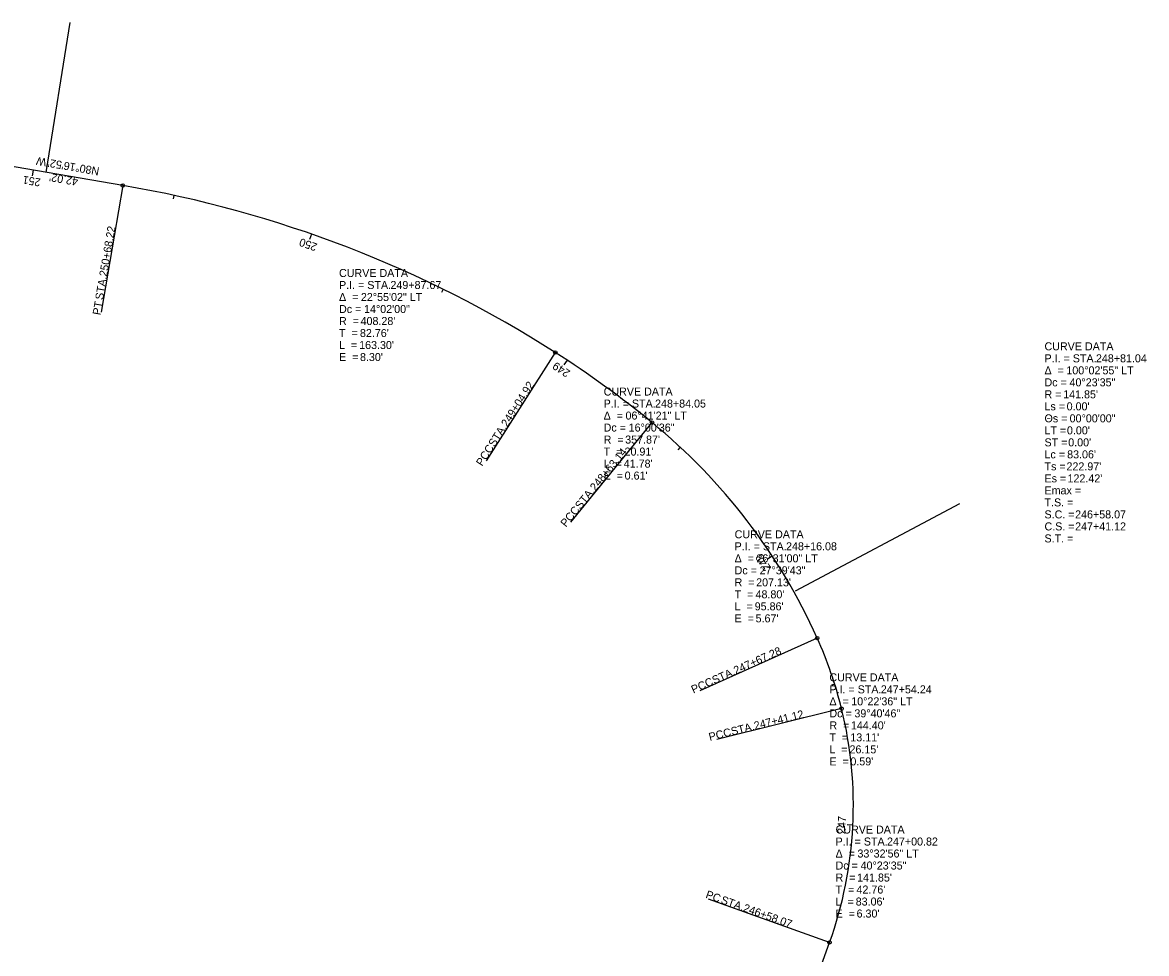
# Model space of a CAD drawing. Extents: x 2479470 to 2480226, y 287083 to 287867.
# Drawn here: x 2479832.4 to 2480225.6, y 287464.3 to 287790 of the extents above; entities that cross this region are included whole.
import ezdxf

# ---------------------------------------------------------------- set-up
doc = ezdxf.new("R2010")
doc.units = 0
for name, color, linetype in [('Default', 7, 'Continuous'), ('DV_X_Lot_Line', 7, 'Continuous'), ('DV_X_Property_Line', 7, 'Continuous'), ('GE_X_Alignment_100_Cardinal_Points', 7, 'Continuous'), ('GE_X_Alignment_100_Curve_Data', 7, 'Continuous'), ('GE_X_Alignment_100_Distances', 7, 'Continuous'), ('GE_X_Alignment_100_Stations', 7, 'Continuous')]:
    doc.layers.add(name, color=color, linetype=linetype)

msp = doc.modelspace()

# ---------------------------------------------------------------- linework, layer by layer
at = {"layer": 'Default'}
msp.add_line((2480102.75, 287591.14), (2480160.32, 287621.66), dxfattribs=at)
msp.add_lwpolyline([(2479840.68, 287737.46), (2479840.79, 287738.22), (2479849.04, 287789.97)], dxfattribs=at)
at = {"layer": 'DV_X_Lot_Line'}
for p, q in [((2479867.44, 287732.95), (2479826.02, 287740.04)), ((2480091.52, 287403.39), (2480114.72, 287468.16))]:
    msp.add_line(p, q, dxfattribs=at)
for centre, radius, start, end in [((2479798.95, 287330.45), 408.28, 57.4266, 80.3437), ((2479826.09, 287372.93), 357.87, 50.7375, 57.4266), ((2479921.5, 287489.65), 207.13, 24.2208, 50.7375), ((2479978.7, 287515.38), 144.4, 13.844, 24.2208), ((2479981.18, 287515.99), 141.85, 340.2952, 13.844)]:
    msp.add_arc(centre, radius, start, end, dxfattribs=at)
at = {"layer": 'GE_X_Alignment_100_Cardinal_Points'}
for p, q in [((2479867.44, 287732.95), (2479859.84, 287688.59)), ((2480018.76, 287674.51), (2479994.54, 287636.59)), ((2480052.58, 287650.02), (2480024.1, 287615.17)), ((2480110.39, 287574.62), (2480069.35, 287556.16)), ((2480118.91, 287549.93), (2480075.21, 287539.16)), ((2480114.72, 287468.16), (2480072.36, 287483.34))]:
    msp.add_line(p, q, dxfattribs=at)
for centre in [(2479867.44, 287732.95), (2480018.76, 287674.51), (2480052.58, 287650.02), (2480110.39, 287574.62), (2480118.91, 287549.93), (2480114.72, 287468.16)]:
    msp.add_circle(centre, 0.6, dxfattribs=at)
at = {"layer": 'GE_X_Alignment_100_Stations'}
for p, q in [((2479836.11, 287738.31), (2479835.78, 287736.34)), ((2479885.33, 287729.49), (2479885.07, 287728.32)), ((2479933.42, 287715.95), (2479932.77, 287714.06)), ((2479979.51, 287696.64), (2479978.98, 287695.56)), ((2480022.89, 287671.84), (2480021.79, 287670.17)), ((2480062.48, 287641.39), (2480061.66, 287640.51)), ((2480094.67, 287603.28), (2480093, 287602.18)), ((2480116.52, 287558.48), (2480115.37, 287558.12)), ((2480122.86, 287509.14), (2480120.86, 287509.24))]:
    msp.add_line(p, q, dxfattribs=at)

# ---------------------------------------------------------------- texts
at = {"layer": 'DV_X_Property_Line'}
msp.add_text('N80°16\'52"W', height=2.8, rotation=170.2811, dxfattribs=at).set_placement((2479859.4, 287739.19))
at = {"layer": 'GE_X_Alignment_100_Cardinal_Points'}
for s, rotation, p in [('250+68.22', 80.2811, (2479861.92, 287700.94)), (' STA. ', 80.2811, (2479860.34, 287691.75)), ('PT', 80.2811, (2479859.61, 287687.46)), ('249+04.92', 57.4266, (2480001.95, 287648.26)), (' STA. ', 57.4266, (2479996.93, 287640.4)), ('PCC', 57.4266, (2479993.18, 287634.53)), ('248+63.14', 50.7375, (2480032.78, 287625.85)), (' STA. ', 50.7375, (2480026.88, 287618.63)), ('PCC', 50.7375, (2480022.47, 287613.24)), ('247+67.28', 24.2208, (2480081.91, 287561.85)), (' STA. ', 24.2208, (2480073.41, 287558.02)), ('PCC', 24.2208, (2480067.06, 287555.17)), ('247+41.12', 13.844, (2480088.63, 287542.51)), (' STA. ', 13.844, (2480079.57, 287540.28)), ('PCC', 13.844, (2480072.82, 287538.61)), ('PC', 340.2952, (2480071.13, 287483.81)), (' STA. ', 340.2952, (2480075.46, 287482.26)), ('246+58.07', 340.2952, (2480084.24, 287479.12))]:
    msp.add_text(s, height=2.8, rotation=rotation, dxfattribs=at).set_placement(p)
at = {"layer": 'GE_X_Alignment_100_Curve_Data'}
for s, p in [('CURVE DATA', (2479943.1, 287700.93)), ('P.I. = STA. ', (2479943.1, 287696.73)), ('249+87.67', (2479961.09, 287696.73)), ('Δ  = ', (2479943.1, 287692.53)), ('22°55\'02" LT', (2479950.75, 287692.53)), ('Dc = ', (2479943.1, 287688.33)), ('14°02\'00"', (2479951.85, 287688.33)), ('R  = ', (2479943.1, 287684.13)), ("408.28'", (2479950.64, 287684.13)), ('T  = ', (2479943.1, 287679.93)), ("82.76'", (2479950.42, 287679.93)), ('L  = ', (2479943.1, 287675.73)), ("163.30'", (2479950.14, 287675.73)), ('CURVE DATA', (2480189.9, 287675.28)), ('E  = ', (2479943.1, 287671.53)), ("8.30'", (2479950.44, 287671.53)), ('P.I. = STA. ', (2480189.9, 287671.08)), ('248+81.04', (2480207.89, 287671.08)), ('Δ  = ', (2480189.9, 287666.88)), ('100°02\'55" LT', (2480197.55, 287666.88)), ('CURVE DATA', (2480035.67, 287659.46)), ('Dc = ', (2480189.9, 287662.68)), ('40°23\'35"', (2480198.65, 287662.68)), ('P.I. = STA. ', (2480035.67, 287655.26)), ('248+84.05', (2480053.66, 287655.26)), ('R = ', (2480189.9, 287658.48)), ("141.85'", (2480196.44, 287658.48)), ('Δ  = ', (2480035.67, 287651.06)), ('06°41\'21" LT', (2480043.32, 287651.06)), ('Ls = ', (2480189.9, 287654.28)), ("0.00'", (2480197.65, 287654.28)), ('Θs = ', (2480189.9, 287650.08)), ('00°00\'00"', (2480198.69, 287650.08)), ('Dc = ', (2480035.67, 287646.86)), ('16°00\'36"', (2480044.42, 287646.86)), ('LT = ', (2480189.9, 287645.88)), ("0.00'", (2480197.75, 287645.88)), ('R  = ', (2480035.67, 287642.66)), ("357.87'", (2480043.21, 287642.66)), ('ST = ', (2480189.9, 287641.68)), ("0.00'", (2480198.2, 287641.68)), ('T  = ', (2480035.67, 287638.46)), ("20.91'", (2480042.99, 287638.46)), ('Lc = ', (2480189.9, 287637.48)), ("83.06'", (2480197.82, 287637.48)), ('L  = ', (2480035.67, 287634.26)), ("41.78'", (2480042.71, 287634.26)), ('Ts = ', (2480189.9, 287633.28)), ("222.97'", (2480197.59, 287633.28)), ('E  = ', (2480035.67, 287630.06)), ("0.61'", (2480043.02, 287630.06)), ('Es = ', (2480189.9, 287629.08)), ("122.42'", (2480197.95, 287629.08)), ('Emax = ', (2480189.9, 287624.88)), ('T.S. = ', (2480189.9, 287620.68)), ('S.C. = ', (2480189.9, 287616.48)), ('246+58.07', (2480200.61, 287616.48)), ('C.S. = ', (2480189.9, 287612.28)), ('247+41.12', (2480200.61, 287612.28)), ('CURVE DATA', (2480081.49, 287609.52)), ('S.T. = ', (2480189.9, 287608.08)), ('P.I. = STA. ', (2480081.49, 287605.32)), ('248+16.08', (2480099.48, 287605.32)), ('Δ  = ', (2480081.49, 287601.12)), ('26°31\'00" LT', (2480089.13, 287601.12)), ('Dc = ', (2480081.49, 287596.92)), ('27°39\'43"', (2480090.23, 287596.92)), ('R  = ', (2480081.49, 287592.72)), ("207.13'", (2480089.02, 287592.72)), ('T  = ', (2480081.49, 287588.52)), ("48.80'", (2480088.81, 287588.52)), ('L  = ', (2480081.49, 287584.32)), ("95.86'", (2480088.52, 287584.32)), ("5.67'", (2480088.83, 287580.12)), ('E  = ', (2480081.49, 287580.12)), ('CURVE DATA', (2480114.65, 287559.48)), ('P.I. = STA. ', (2480114.65, 287555.28)), ('247+54.24', (2480132.64, 287555.28)), ('Δ  = ', (2480114.65, 287551.08)), ('10°22\'36" LT', (2480122.29, 287551.08)), ('Dc = ', (2480114.65, 287546.88)), ('39°40\'46"', (2480123.39, 287546.88)), ('R  = ', (2480114.65, 287542.68)), ("144.40'", (2480122.18, 287542.68)), ('T  = ', (2480114.65, 287538.48)), ("13.11'", (2480121.97, 287538.48)), ('L  = ', (2480114.65, 287534.28)), ("26.15'", (2480121.68, 287534.28)), ('E  = ', (2480114.65, 287530.08)), ("0.59'", (2480121.99, 287530.08)), ('CURVE DATA', (2480116.81, 287506.25)), ('P.I. = STA. ', (2480116.81, 287502.05)), ('247+00.82', (2480134.8, 287502.05)), ('Δ  = ', (2480116.81, 287497.85)), ('33°32\'56" LT', (2480124.46, 287497.85)), ('Dc = ', (2480116.81, 287493.65)), ('40°23\'35"', (2480125.56, 287493.65)), ('R  = ', (2480116.81, 287489.45)), ("141.85'", (2480124.35, 287489.45)), ('T  = ', (2480116.81, 287485.25)), ("42.76'", (2480124.13, 287485.25)), ('L  = ', (2480116.81, 287481.05)), ("83.06'", (2480123.85, 287481.05)), ('E  = ', (2480116.81, 287476.85)), ("6.30'", (2480124.16, 287476.85))]:
    msp.add_text(s, height=2.8, dxfattribs=at).set_placement(p)
at = {"layer": 'GE_X_Alignment_100_Distances'}
msp.add_text("42.02'", height=2.8, rotation=170.2811, dxfattribs=at).set_placement((2479851.97, 287735.56))
at = {"layer": 'GE_X_Alignment_100_Stations'}
for s, rotation, p in [('251', 170.2811, (2479838.87, 287735.3)), ('250', 160.7702, (2479935.69, 287712.52)), ('249', 146.6396, (2480024.21, 287667.97)), ('248', 123.2731, (2480094.36, 287599.19)), ('247', 87.2329, (2480120.21, 287506.03))]:
    msp.add_text(s, height=2.8, rotation=rotation, dxfattribs=at).set_placement(p)

doc.saveas('drawing.dxf')
